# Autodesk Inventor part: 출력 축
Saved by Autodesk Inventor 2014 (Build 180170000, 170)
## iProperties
Created: 2026-04
Part Number: 출력 축
Material: 일반
Document SubType Name: Modeling
Designer: dg
Density: 1 g/cm^3
Appearance: 기본값
Author: dg
Author: jhkim
Creation Date: 2026-03-27
Sending System: Autodesk Inventor 2026
Preprocessor: ST-DEVELOPER v20.1
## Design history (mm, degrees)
node "출력 축1"
node "솔리드1"
node "기준1"
